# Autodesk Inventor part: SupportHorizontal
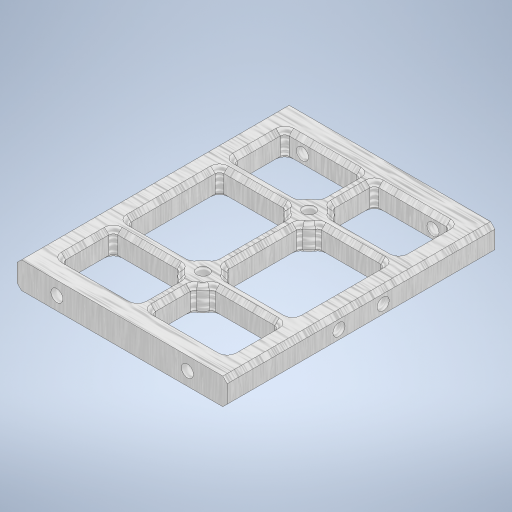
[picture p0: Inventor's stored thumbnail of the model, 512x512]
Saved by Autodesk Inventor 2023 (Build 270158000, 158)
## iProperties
Created: 2023-10
Part Number: SupportHorizontal
Material: Aluminum 7075
Document SubType Name: Modeling
Designer: tornqvih
Density: 2.81 g/cm^3
Appearance: Satin - Brushed Heavy
Author: tornqvih
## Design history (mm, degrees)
sketch "Sketch1"
  geometry: L1 (47.5, 60.5)-(-47.5, 60.5); L2 (-47.5, 60.5)-(-47.5, -60.5); L3 (-47.5, -60.5)-(47.5, -60.5); L4 (47.5, -60.5)-(47.5, 60.5); L5 (47.5, 60.5)-(-47.5, -60.5); L6 (-47.5, 60.5)-(47.5, -60.5); 1 further point
  constraints: 12 end point, 2 midpoint, 2 parallel, 1 horizontal, 1 perpendicular
  dimensions: "d0" = 121 distance of L3.end L1.start; "d1" = 95 distance of L1.start L1.end
extrude "Extrusion1" new body sketch "Sketch1" distance "d2" = 12; taper "d3" = 0 deg
sketch "Sketch2"
  geometry: L1 (-37.5, 50.5)-(37.5, 50.5); L2 (37.5, 50.5)-(37.5, -50.5); L3 (37.5, -50.5)-(-37.5, -50.5); L4 (-37.5, -50.5)-(-37.5, 50.5); L5 (0, 84.7)-(0, -84.7) reference; L6 (-66.5, 0)-(66.5, 0) reference; L7 (47.5, 60.5)-(-47.5, 60.5) reference; L8 (-47.5, 60.5)-(-47.5, -60.5) reference
  constraints: 8 end point, 2 symmetric about line, 1 horizontal, 1 vertical
  dimensions: "d4" = 10 distance between parallel lines of L7 L1; "d5" = 10 distance between parallel lines of L8 L4
extrude "Extrusion2" cut sketch "Sketch2" distance "d10" = 12; taper "d11" = 0 deg
sketch "Sketch7"
  geometry: L1 (0, -70.7)-(0, 70.7) reference; L2 (52.5, 0)-(-52.5, 0) reference; L3 (-37.5, 50.5)-(37.5, 50.5) reference; L4 (3, 50.5)-(3, -50.5); L5 (-3, 50.5)-(-3, -50.5); L6 (-37.5, 27)-(37.5, 27); L7 (37.5, -50.5)-(37.5, 50.5) reference; L8 (-37.5, 21)-(37.5, 21); L9 (-37.5, -21)-(37.5, -21); L10 (-37.5, -27)-(37.5, -27); L11 (-37.5, -50.5)-(37.5, -50.5) reference; L12 (-37.5, -50.5)-(-37.5, 50.5) reference; L13 (37.5, -50.5)-(-37.5, -50.5) reference; C1 r 8 at (0, 24); C2 r 8 at (0, -24); 20 further points
  constraints: 12 end point, 8 point on line, 7 symmetric about line, 2 centre point, 2 horizontal
  dimensions: "d54" = 16 diameter of C1; "d55" = 24 distance of point (0, 0) C1.centre; "d56" = 16 diameter of C2; "d62" = 3 distance between parallel lines of L1 L4; "d64" = 3 distance from line of C1.centre L6; "d65" = 3 distance from line of C1.centre L8
extrude "Extrusion3" join sketch "Sketch7" distance "d57" = 12; taper "d58" = 0 deg
sketch "Sketch3"
  geometry: L1 (0, 12)-(95, 12) reference; L2 (0, 0)-(0, 12) reference; L3 (95, 0)-(95, 12) reference; 2 further points
  constraints: 1 horizontal alignment
  dimensions: "d12" = 6 distance from line of L1 point (18, 6); "d13" = 18 distance from line of L2 point (18, 6); "d14" = 18 distance from line of L3 point (77, 6)
hole "Hole1" sketch "Sketch3" at (18, 6), (77, 6) diameter "d15" = 5.5; stored, may be unused: countersink angle "d19" = 90 deg, drill point angle "d21" = 118 deg; dims "d16" = 6, "d17" = 4, "d18" = 2, "d20" = 10
sketch "Sketch4"
  geometry: L1 (0, 12)-(95, 12) reference; L2 (0, 0)-(0, 12) reference; L3 (95, 0)-(95, 12) reference; C1 r 2.75 at (18, 6) reference; C2 r 2.75 at (77, 6) reference; 2 further points
  constraints: 2 coincident
hole "Hole2" sketch "Sketch4" at (18, 6), (77, 6) diameter "d25" = 5.5; stored, may be unused: countersink angle "d29" = 90 deg, drill point angle "d31" = 118 deg; dims "d26" = 6, "d27" = 4, "d28" = 2, "d30" = 10
sketch "Sketch5"
  geometry: L1 (0, 12)-(121, 12) reference; L2 (0, 0)-(0, 12) reference; 5 further points
  constraints: 2 horizontal alignment, 1 midpoint
  dimensions: "d32" = 6 distance from line of L1 point (60.5, 6); "d33" = 10 distance of point (50.5, 6) point (60.5, 6); "d34" = 10 distance of point (70.5, 6) point (60.5, 6); "d53" = 60.5 distance from line of L2 point (60.5, 6)
hole "Hole3" sketch "Sketch5" at (50.5, 6), (70.5, 6) diameter "d35" = 5.5; stored, may be unused: countersink angle "d39" = 90 deg, drill point angle "d41" = 118 deg; dims "d36" = 6, "d37" = 4, "d38" = 2, "d40" = 10
sketch "Sketch6"
  geometry: L1 (-66.5, 0)-(66.5, 0) reference; L2 (0, 84.7)-(0, -84.7) reference; 3 further points
  constraints: 1 point on line, 1 symmetric about line
  dimensions: "d66" = 24 distance from line of L1 point (0, -24)
hole "Hole4" sketch "Sketch6" at (0, 24), (0, -24) diameter "d46" = 5.5; stored, may be unused: countersink angle "d50" = 90 deg, drill point angle "d52" = 118 deg; dims "d47" = 6, "d48" = 4, "d49" = 2, "d51" = 10
fillet "Fillet1" dims "d67" = 2
chamfer "Chamfer1" distance "d70" = 2; stored, may be unused: second distance "d71" = 2, angle "d72" = 45 deg
body "Solid1"
